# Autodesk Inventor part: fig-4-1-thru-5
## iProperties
Created: 2004-05
Part Number: fig-4-1-thru-5
Document SubType Name: Modeling
Designer: CADCIM Technologies
Manufacturer: Standard
Standards Organization: Custom
Author: CADCIM Technologies
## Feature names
1. Extrusion1
2. Fillet1
